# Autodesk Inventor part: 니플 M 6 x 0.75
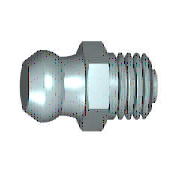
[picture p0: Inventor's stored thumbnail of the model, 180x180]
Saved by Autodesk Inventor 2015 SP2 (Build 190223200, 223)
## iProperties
IsCustomPart: 1
Created: 2012-02
Part Number: 니플 M 6 x 0.75
Material: 강철, 연강
Description: 윤활 니플, 원추 유형 A
Document SubType Name: Modeling
Standard: JIS B 1575
Designer: mduedu
Standards Organization: JIS
Language: ko-KR
Size Designation: MT 6 x 0.75
Categories: <MemberInstance><Categories><Category DisplayName="기타 부품" InternalName="5aa15e00-363f-49f2-933f-16f664388e3f" Mnemonic="OTHER"><Category DisplayName="그리스 부속품" I
Density: 1 g/cm^3
Appearance: 강철
Author: mduedu
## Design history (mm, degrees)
sketch "스케치1"
  geometry: L1 (-8.8, 0)-(-8.8, 2.4); L2 (-8.8, 2.4)-(-7.335, 3.202); L3 (-8.8, 0)-(4.7, 0); L4 (4.7, 0)-(4.7, 1.5); L5 (4.7, 1.5)-(4, 1.5); L6 (4, 1.5)-(4, 3); L7 (4, 3)-(0, 3); L8 (-11.5, 0)-(7.4, 0) reference; L9 (0, -1.733)-(0, 10.398) reference; L10 (-3, 3.5)-(0, 3.5); L11 (0, 3.5)-(0, 3); A1 r 3.3 centre (-6.535, 0) between (-4.789, 2.8) and (-7.335, 3.202); A2 r 6 centre (-6.053, 8.665) between (-4.789, 2.8) and (-3, 3.5)
  constraints: 18 end point, 5 perpendicular, 4 point on circle, 2 centre point, 2 parallel, 2 point on line, 1 collinear, 1 vertical
  dimensions: "d0" = 13.5 distance between parallel lines of L1 L4 (= GL); "d1" = 5.6 diameter of A1.start L3 (= KGB2); "d2" = 0.7 distance between parallel lines of L4 L6 (= PHH); "d3" = 3 diameter of L5 L3 (= 0.5 x NND); "d4" = 6 diameter of L7 L3 (= NND); "d5" = 6.6 dimension on A1 L3 (= KR); "d6" = 4.8 diameter of L1.end L3 (= KGB1); "d7" = 6 radius of A2 (= RBN); "d11" = 7 diameter of L10.start L3 (= SW); "d14" = 3 distance of L10.start L10.end (= KOH); "d15" = 4 distance between parallel lines of L6 L11 (= NLG); "d61" = 7.33505 distance from line of L9 L2.end (computed from KGB1, KR, PHH, GL, NLG, VERS); "d62" = 6.53505 distance from line of L9 A1.centre (computed from NLG, GL, PHH, KR, KGB1)
revolve "본체" sketch "스케치1" stored, may be unused: angle "d25" = 90 deg
sketch "스케치2"
  geometry: L1 (2.021, 3.5)-(4.041, 0); L2 (4.041, 0)-(2.021, -3.5); L3 (2.021, -3.5)-(-2.021, -3.5); L4 (-2.021, -3.5)-(-4.041, 0); L5 (-4.041, 0)-(-2.021, 3.5); L6 (-2.021, 3.5)-(2.021, 3.5); C1 r 3.5 at (0, 0) reference; 1 further point
  constraints: 12 end point, 1 coincident, 1 horizontal, 1 tangent, 11 other
extrude "머리" join sketch "스케치2" distance "d17" = 3 (= KOH); taper "d18" = 0 deg
sketch "스케치3"
  geometry: L1 (2.687, 4.041)-(3, 4.041); L2 (3, 4.041)-(3, 3.5); L3 (3, 3.5)-(2.687, 4.041); L4 (0.313, 4.041)-(0, 4.041); L5 (0, 4.041)-(0, 3.5); L6 (0, 3.5)-(0.313, 4.041); L7 (3.6, 0)-(-0.6, 0) reference; L8 (0, 4.041)-(0, 2.021) reference; L9 (0, 4.041)-(3, 4.041) reference; L10 (3, 3.031)-(3, 4.041) reference
  constraints: 12 end point, 4 collinear, 3 perpendicular, 1 horizontal
  dimensions: "d19" = 3.5 distance from line of L5.end L7 (= 0.5 x SW); "d20" = 3.5 distance from line of L2.end L7 (= 0.5 x SW); "d21" = 30 deg angle of L6 L5; "d22" = 30 deg angle of L2 L3
revolve "모따기1" sketch "스케치3" stored, may be unused: angle "d56" = 90 deg
body "Solid1"
fillet "모깎기1" dims "d8" = 0.2 (= RR)
feature "스레드1" dims "d9" = 3.53991 (= NLG - GAL), "d10" = 0
chamfer "모따기2" distance "d23" = 0.46009 (= -0.5 x GD1 + 0.5 x NND); stored, may be unused: angle "d24" = 45 deg, second distance "d59" = 0.46009 (= -0.5 x GD1 + 0.5 x NND)
other parameters: "NLG" = 4 [user parameter; used in 4 equation terms], "GL" = 13.5 [user parameter; used in 3 equation terms], "NND" = 6 [user parameter; used in 4 equation terms], "KGB1" = 4.8 [user parameter; used in 3 equation terms], "KGB2" = 5.6 [user parameter; used in 1 equation term], "VERS" = 0.8 [user parameter; used in 1 equation term], "KR" = 6.6 [user parameter; used in 3 equation terms], "RBN" = 6 [user parameter; used in 1 equation term], "SW" = 7 [user parameter; used in 3 equation terms], "KOH" = 3 [user parameter; used in 2 equation terms], "GAL" = 0.46009 (= 0.61345 x PTC) [user parameter; used in 1 equation term], "FAWI" = 45 deg [user parameter], "PHH" = 0.7 [user parameter; used in 3 equation terms], "GD1" = 5.07983 (= THREADDIA - 1.2269 x PTC) [user parameter; used in 2 equation terms], "RR" = 0.2 [user parameter; used in 1 equation term], "d12" = 0, "d13" = 0, "GUL" = 0.46009 (= 0.61345 x PTC) [user parameter], "TPU" = 13.33333 (computed from PTC) [user parameter], "DULO" = 1.5 [user parameter], "PTC" = 0.75 [user parameter; used in 4 equation terms], "GEL" = 4 [user parameter], "THREADDIA" = 6 [user parameter; used in 1 equation term], "TOA" = 30 deg [user parameter]
